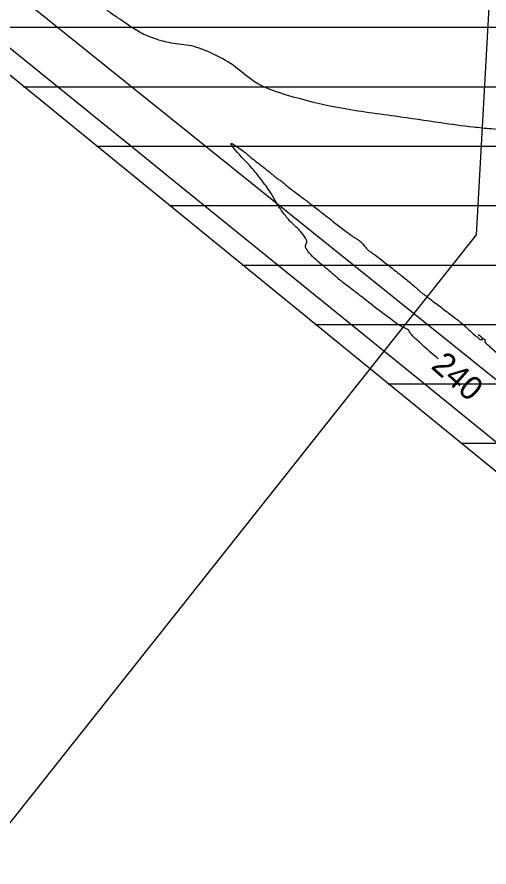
# Model space of a CAD drawing. Extents: x -478464 to -472469, y -1118040 to -1113785.
# Drawn here: x -477003.6 to -476924.2, y -1115204.8 to -1115061.8 of the extents above; entities that cross this region are included whole.
import ezdxf

# ---------------------------------------------------------------- set-up
doc = ezdxf.new("R2010")
doc.units = 0
for name, color, linetype in [('meliorace', 7, 'Continuous'), ('plyn_vtl', 7, 'Continuous'), ('silnice', 7, 'Continuous'), ('telekomunikační kabel_O2', 7, 'Continuous'), ('Vrstevnice_hlavni', 7, 'Continuous'), ('Vrstevnice_popis', 7, 'Continuous')]:
    doc.layers.add(name, color=color, linetype=linetype)

msp = doc.modelspace()

# ---------------------------------------------------------------- linework, layer by layer
at = {"layer": 'meliorace'}
for p, q in [((-477014.727, -1115063.499), (-476601.498, -1115063.499)), ((-477002.469, -1115073.499), (-476619.045, -1115073.499)), ((-476990.212, -1115083.499), (-476636.592, -1115083.499)), ((-476977.954, -1115093.499), (-476653.316, -1115093.499)), ((-476965.697, -1115103.499), (-476667.072, -1115103.499)), ((-476953.439, -1115113.499), (-476680.827, -1115113.499)), ((-476941.182, -1115123.499), (-476694.583, -1115123.499)), ((-476928.924, -1115133.499), (-476791.246, -1115133.499))]:
    msp.add_line(p, q, dxfattribs=at)
msp.add_lwpolyline([(-476300.545, -1114963.207), (-476368.477, -1114983.187), (-476385.793, -1114988.182), (-476407.105, -1114989.43), (-476428.417, -1114990.679), (-476466.247, -1114999.171), (-476589.855, -1115056.864), (-476650.329, -1115091.328), (-476713.19, -1115137.026), (-476738.506, -1115158.512), (-476785.126, -1115129.041), (-476863.979, -1115186.483), (-477017.961, -1115060.861)], dxfattribs=at)
at = {"layer": 'plyn_vtl'}
msp.add_lwpolyline([(-477136.632, -1115358.745), (-477083.67, -1115296.91), (-476926.35, -1115098.44), (-476915.085, -1114895.754)], dxfattribs=at)
at = {"layer": 'silnice'}
msp.add_lwpolyline([(-476261.922, -1115907.288), (-476366.595, -1115823.727), (-476390.845, -1115803.24), (-476425.665, -1115718.481), (-476494.983, -1115557.356), (-476524.795, -1115496.42), (-476580.823, -1115418.032), (-476641.911, -1115352.297), (-476741.891, -1115268.259), (-476824.194, -1115202.313), (-477005.33, -1115056.573), (-477039.82, -1115023.276), (-477040.729, -1115022.048)], dxfattribs=at)
at = {"layer": 'telekomunikační kabel_O2'}
msp.add_line((-476985.91, -1115082.25), (-476984.82, -1115083.13), dxfattribs=at)
msp.add_line((-476985.91, -1115082.25), (-476984.82, -1115083.13), dxfattribs=at)
for points in [[(-477010.07, -1115062.67), (-476985.91, -1115082.25)], [(-476984.82, -1115083.13), (-476978.14, -1115088.55), (-476938.13, -1115120.98)], [(-476938.13, -1115120.98), (-476897.97, -1115153.62), (-476861.558, -1115183.224)]]:
    msp.add_lwpolyline(points, dxfattribs=at)
at = {"layer": 'Vrstevnice_hlavni'}
for points in [[(-476873.251, -1115143.677), (-476873.507, -1115142.01), (-476873.554, -1115139.102), (-476873.522, -1115134.12), (-476873.41, -1115127.063), (-476873.808, -1115122.086), (-476874.717, -1115119.19), (-476876.136, -1115118.374), (-476877.354, -1115117.171), (-476878.371, -1115115.579), (-476879.185, -1115113.6), (-476882.364, -1115111.475), (-476887.908, -1115109.205), (-476895.815, -1115106.789), (-476902.242, -1115103.761), (-476907.186, -1115100.12), (-476910.649, -1115095.867), (-476913.66, -1115091.883), (-476916.218, -1115088.167), (-476918.324, -1115084.72), (-476919.725, -1115082.379), (-476920.421, -1115081.145), (-476920.412, -1115081.017), (-476920.426, -1115080.932), (-476920.462, -1115080.891), (-476920.521, -1115080.893), (-476920.576, -1115080.895), (-476920.627, -1115080.896), (-476920.674, -1115080.898), (-476921.736, -1115080.799), (-476923.814, -1115080.599), (-476926.907, -1115080.3), (-476932.302, -1115079.591), (-476940, -1115078.472), (-476950, -1115076.944), (-476957.876, -1115075.006), (-476963.629, -1115072.657), (-476967.259, -1115069.897), (-476970.802, -1115067.892), (-476974.259, -1115066.643), (-476977.631, -1115066.149), (-476980.601, -1115065.341), (-476983.17, -1115064.218), (-476985.338, -1115062.781), (-476986.878, -1115061.747), (-476987.79, -1115061.118), (-476988.074, -1115060.892), (-476988.478, -1115060.587), (-476989.003, -1115060.204), (-476989.648, -1115059.743), (-476990.332, -1115059.246), (-476991.055, -1115058.714), (-476991.817, -1115058.146), (-476992.891, -1115057.395), (-476994.277, -1115056.46), (-476995.976, -1115055.343), (-476997.039, -1115054.593), (-476997.464, -1115054.21), (-476997.254, -1115054.195), (-476998.009, -1115053.437), (-476999.729, -1115051.937), (-477002.416, -1115049.693), (-477004.444, -1115048.001), (-477005.814, -1115046.86), (-477006.527, -1115046.27), (-477007.324, -1115045.723), (-477008.206, -1115045.221), (-477009.173, -1115044.763), (-477009.833, -1115044.445), (-477010.186, -1115044.267), (-477010.232, -1115044.228), (-477010.318, -1115044.158), (-477010.443, -1115044.058), (-477010.608, -1115043.927), (-477010.866, -1115043.703), (-477011.219, -1115043.389), (-477011.666, -1115042.982), (-477011.859, -1115042.654), (-477011.796, -1115042.405), (-477011.479, -1115042.235), (-477011.695, -1115041.846), (-477012.445, -1115041.236), (-477013.729, -1115040.407), (-477014.642, -1115039.799), (-477015.184, -1115039.41), (-477015.355, -1115039.241), (-477015.476, -1115039.117), (-477015.545, -1115039.038), (-477015.564, -1115039.003), (-477015.672, -1115038.875), (-477015.869, -1115038.653), (-477016.157, -1115038.339), (-477016.405, -1115038.07), (-477016.615, -1115037.849), (-477016.786, -1115037.674), (-477017.213, -1115037.282), (-477017.894, -1115036.673)], [(-476932.792, -1115119.262), (-476935.498, -1115116.888), (-476936.479, -1115116), (-476937.087, -1115115.411), (-476937.323, -1115115.12), (-476937.5, -1115114.875), (-476937.618, -1115114.675), (-476937.677, -1115114.52), (-476937.902, -1115114.338), (-476938.294, -1115114.131), (-476938.853, -1115113.897), (-476940.257, -1115112.944), (-476942.505, -1115111.269), (-476945.599, -1115108.875), (-476947.707, -1115107.241), (-476948.83, -1115106.367), (-476948.968, -1115106.254), (-476949.085, -1115106.163), (-476949.183, -1115106.094), (-476949.259, -1115106.046), (-476949.323, -1115106.009), (-476949.372, -1115105.985), (-476949.408, -1115105.973), (-476949.45, -1115105.944), (-476949.499, -1115105.898), (-476949.555, -1115105.835), (-476949.591, -1115105.789), (-476949.608, -1115105.759), (-476949.604, -1115105.746), (-476949.613, -1115105.727), (-476949.632, -1115105.703), (-476949.663, -1115105.672), (-476949.747, -1115105.601), (-476949.884, -1115105.489), (-476950.074, -1115105.337), (-476950.759, -1115104.761), (-476951.937, -1115103.761), (-476953.608, -1115102.337), (-476954.654, -1115101.176), (-476955.074, -1115100.278), (-476954.868, -1115099.641), (-476955.177, -1115098.795), (-476956.001, -1115097.738), (-476957.339, -1115096.471), (-476958.612, -1115094.975), (-476959.82, -1115093.251), (-476960.962, -1115091.298), (-476962.522, -1115089.122), (-476964.501, -1115086.721), (-476966.899, -1115084.097), (-476967.595, -1115083.05), (-476966.591, -1115083.578), (-476963.886, -1115085.683), (-476961.932, -1115087.218), (-476960.727, -1115088.185), (-476960.273, -1115088.582), (-476959.89, -1115088.89), (-476959.578, -1115089.107), (-476959.337, -1115089.235), (-476959.065, -1115089.426), (-476958.762, -1115089.68), (-476958.427, -1115089.997), (-476957.854, -1115090.467), (-476957.042, -1115091.091), (-476955.991, -1115091.868), (-476954.506, -1115092.998), (-476952.585, -1115094.482), (-476950.23, -1115096.32), (-476948.452, -1115097.684), (-476947.252, -1115098.575), (-476946.631, -1115098.991), (-476946.191, -1115099.29), (-476945.932, -1115099.472), (-476945.855, -1115099.535), (-476945.803, -1115099.579), (-476945.774, -1115099.602), (-476945.77, -1115099.605), (-476945.758, -1115099.615), (-476945.738, -1115099.63), (-476945.712, -1115099.651), (-476945.614, -1115099.762), (-476945.445, -1115099.961), (-476945.205, -1115100.25), (-476944.97, -1115100.515), (-476944.74, -1115100.756), (-476944.515, -1115100.974), (-476944.231, -1115101.209), (-476943.887, -1115101.464), (-476943.485, -1115101.736), (-476942.59, -1115102.412), (-476941.204, -1115103.491), (-476939.325, -1115104.974), (-476937.88, -1115106.138), (-476936.869, -1115106.982), (-476936.293, -1115107.506), (-476935.78, -1115107.952), (-476935.331, -1115108.319)], [(-476935.331, -1115108.319), (-476934.947, -1115108.607), (-476934.415, -1115109.009), (-476933.736, -1115109.525), (-476932.909, -1115110.156), (-476932.006, -1115110.842), (-476931.026, -1115111.583), (-476929.968, -1115112.379), (-476928.913, -1115113.236), (-476927.86, -1115114.154), (-476926.808, -1115115.132), (-476926.037, -1115115.767), (-476925.546, -1115116.058), (-476925.335, -1115116.006), (-476925.325, -1115115.864), (-476925.515, -1115115.632), (-476925.905, -1115115.311), (-476926.044, -1115115.192), (-476925.931, -1115115.276), (-476925.565, -1115115.563), (-476925.29, -1115115.779), (-476925.105, -1115115.925), (-476925.01, -1115116.002), (-476924.95, -1115116.053), (-476924.925, -1115116.079), (-476924.935, -1115116.079), (-476924.936, -1115116.133), (-476924.927, -1115116.239), (-476924.909, -1115116.398), (-476924.628, -1115116.734), (-476924.083, -1115117.247), (-476923.275, -1115117.937), (-476921.987, -1115119.01), (-476920.22, -1115120.464), (-476917.972, -1115122.302), (-476916.102, -1115123.736), (-476914.608, -1115124.768), (-476913.49, -1115125.397), (-476912.676, -1115125.868), (-476912.164, -1115126.18), (-476911.956, -1115126.335), (-476911.795, -1115126.454), (-476911.684, -1115126.538), (-476911.62, -1115126.587), (-476910.788, -1115127.262), (-476909.187, -1115128.562), (-476906.818, -1115130.488), (-476904.666, -1115132.215), (-476902.733, -1115133.742), (-476901.019, -1115135.07), (-476899.74, -1115136.063), (-476898.897, -1115136.721), (-476898.49, -1115137.044), (-476897.79, -1115137.566), (-476896.796, -1115138.286), (-476895.509, -1115139.205), (-476894.623, -1115139.837), (-476894.139, -1115140.183), (-476894.056, -1115140.242), (-476893.9, -1115140.355), (-476893.67, -1115140.521), (-476893.367, -1115140.74), (-476893.126, -1115140.887), (-476892.948, -1115140.962), (-476892.834, -1115140.965), (-476892.748, -1115140.977), (-476892.691, -1115140.997), (-476892.664, -1115141.027), (-476892.601, -1115141.034), (-476892.501, -1115141.018), (-476892.364, -1115140.98), (-476892.219, -1115140.91), (-476892.065, -1115140.81), (-476891.902, -1115140.679), (-476891.793, -1115140.591), (-476891.738, -1115140.546), (-476891.737, -1115140.543), (-476891.726, -1115140.55), (-476891.703, -1115140.565), (-476891.671, -1115140.589), (-476891.32, -1115140.854), (-476890.651, -1115141.361), (-476889.664, -1115142.109), (-476889.038, -1115142.693), (-476888.773, -1115143.114), (-476888.869, -1115143.371), (-476888.964, -1115143.585), (-476889.059, -1115143.757), (-476889.154, -1115143.887), (-476889.202, -1115143.998), (-476889.202, -1115144.091), (-476889.154, -1115144.166), (-476889.109, -1115144.273), (-476889.066, -1115144.412), (-476889.025, -1115144.583), (-476888.922, -1115144.761), (-476888.756, -1115144.947)]]:
    msp.add_spline(points, degree=3, dxfattribs=at)

# ---------------------------------------------------------------- texts
at = {"layer": 'Vrstevnice_popis'}
msp.add_text(' 240 ', height=4, rotation=318.58749, dxfattribs=at).set_placement((-476935.257, -1115119.756))

doc.saveas('drawing.dxf')
